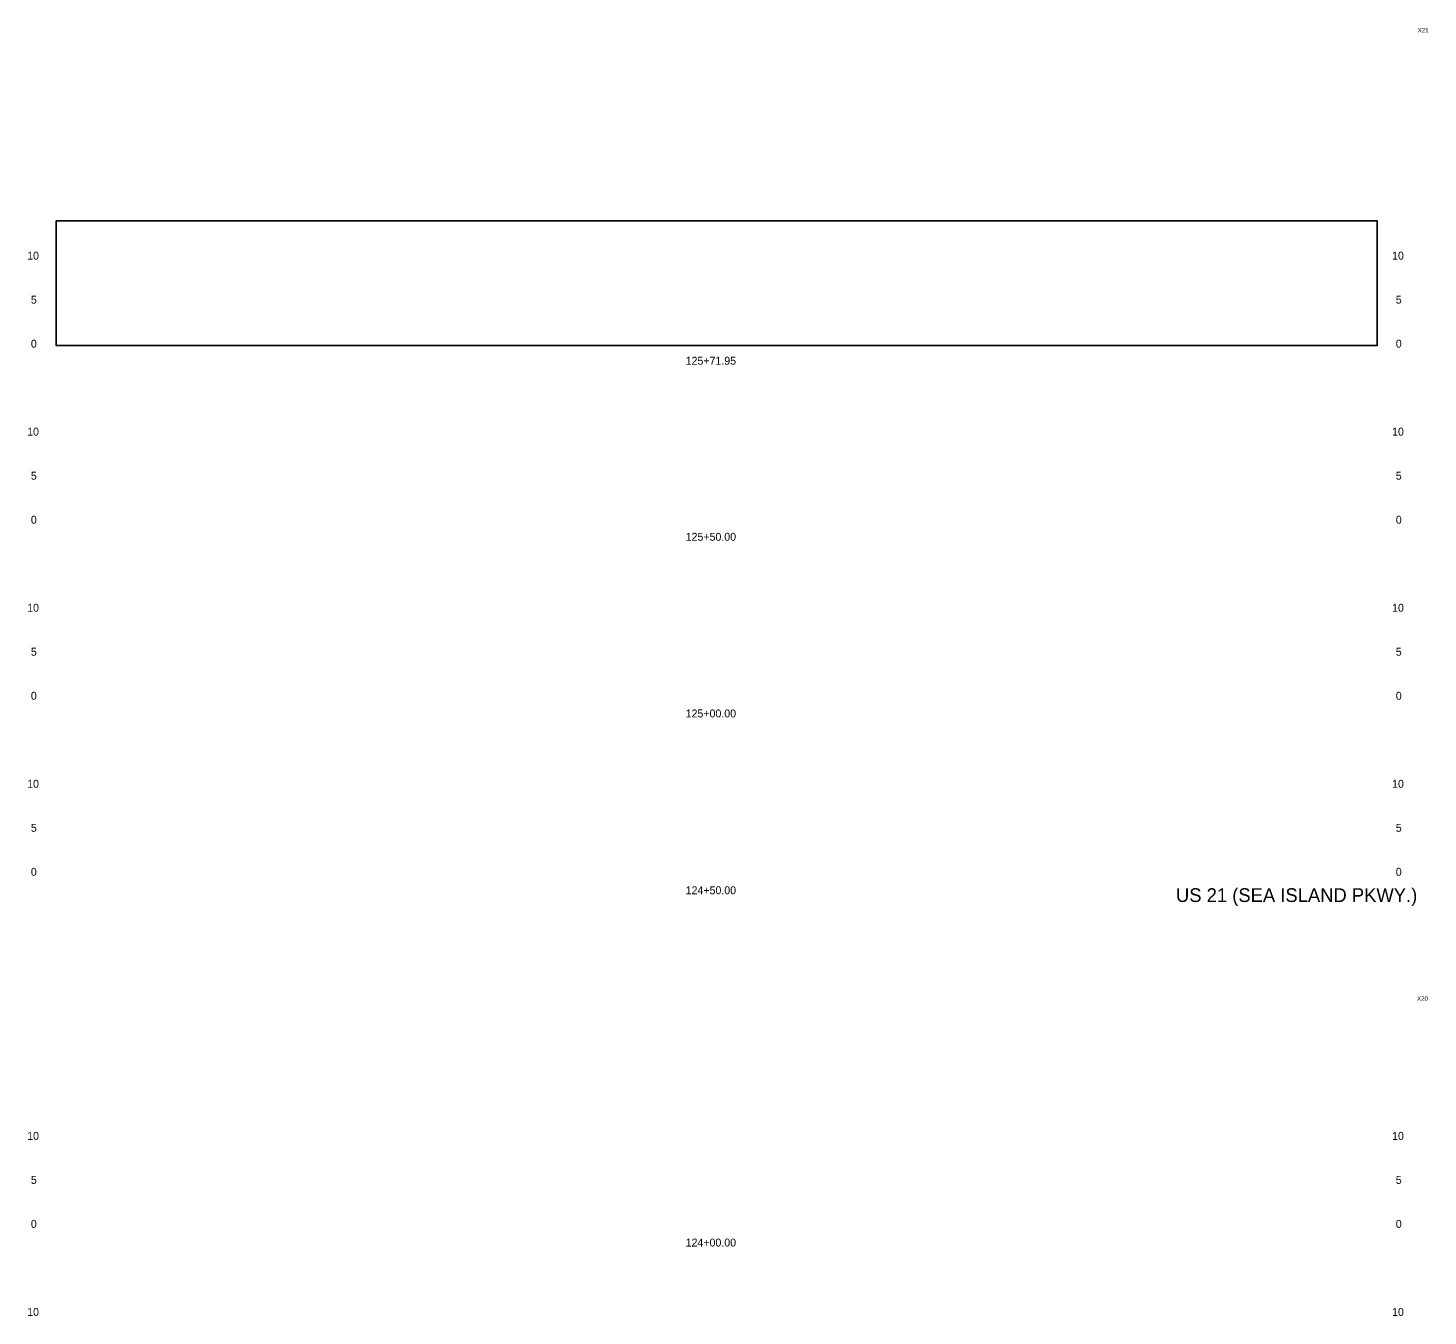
# Model space of a CAD drawing. Extents: x 971 to 1131, y 2203 to 6043.
# Drawn here: x 971.5 to 1130.5, y 5896.9 to 6043.2 of the extents above; entities that cross this region are included whole.
import ezdxf

# ---------------------------------------------------------------- set-up
doc = ezdxf.new("R2010")
doc.units = 0
for name, color, linetype in [('RD_SHT_ShtClip', 7, 'Continuous'), ('RD_SHT_TX', 7, 'Continuous'), ('RD_XS_TX_Station', 7, 'Continuous')]:
    doc.layers.add(name, color=color, linetype=linetype)

msp = doc.modelspace()

# ---------------------------------------------------------------- linework, layer by layer
at = {"layer": 'RD_SHT_ShtClip'}
msp.add_lwpolyline([(974.73, 6021.26), (1124.73, 6021.26), (1124.73, 6007.11), (974.73, 6007.11)], close=True, dxfattribs=at)

# ---------------------------------------------------------------- texts
at = {"layer": 'RD_SHT_TX'}
for s, p in [('X21', (1129.34, 6042.68)), ('X20', (1129.26, 5932.68))]:
    msp.add_text(s, height=0.5, rotation=360, dxfattribs=at).set_placement(p)
for s, height, p in [('10', 0.9, (971.42, 6016.87)), ('10', 0.9, (1126.42, 6016.87)), ('5', 0.9, (971.84, 6011.87)), ('5', 0.9, (1126.84, 6011.87)), ('0', 0.9, (971.84, 6006.87)), ('0', 0.9, (1126.84, 6006.87)), ('10', 0.9, (971.42, 5996.87)), ('10', 0.9, (1126.42, 5996.87)), ('5', 0.9, (971.84, 5991.87)), ('5', 0.9, (1126.84, 5991.87)), ('0', 0.9, (971.84, 5986.87)), ('0', 0.9, (1126.84, 5986.87)), ('10', 0.9, (971.42, 5976.87)), ('10', 0.9, (1126.42, 5976.87)), ('5', 0.9, (971.84, 5971.87)), ('5', 0.9, (1126.84, 5971.87)), ('0', 0.9, (971.84, 5966.87)), ('0', 0.9, (1126.84, 5966.87)), ('10', 0.9, (971.42, 5956.87)), ('10', 0.9, (1126.42, 5956.87)), ('5', 0.9, (971.84, 5951.87)), ('5', 0.9, (1126.84, 5951.87)), ('0', 0.9, (971.84, 5946.87)), ('0', 0.9, (1126.84, 5946.87)), ('US 21 (SEA ISLAND PKWY.)', 1.5625, (1101.88, 5943.89)), ('10', 0.9, (971.42, 5916.87)), ('10', 0.9, (1126.42, 5916.87)), ('5', 0.9, (971.84, 5911.87)), ('5', 0.9, (1126.84, 5911.87)), ('0', 0.9, (971.84, 5906.87)), ('0', 0.9, (1126.84, 5906.87)), ('10', 0.9, (971.42, 5896.87)), ('10', 0.9, (1126.42, 5896.87))]:
    msp.add_text(s, height=height, dxfattribs=at).set_placement(p)
at = {"layer": 'RD_XS_TX_Station'}
for s, p in [('125+71.95', (1046.2, 6004.93)), ('125+50.00', (1046.2, 5984.93)), ('125+00.00', (1046.2, 5964.86)), ('124+50.00', (1046.2, 5944.77)), ('124+00.00', (1046.2, 5904.75))]:
    msp.add_text(s, height=0.9, dxfattribs=at).set_placement(p)

doc.saveas('drawing.dxf')
